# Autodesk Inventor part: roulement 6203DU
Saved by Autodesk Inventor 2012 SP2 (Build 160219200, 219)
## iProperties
Created: 2013-04
Part Number: roulement 6203DU
Material: Default
Document SubType Name: Modeling
Designer: papa
Density: 1 g/cm^3
Mass: 8.8924 g
Surface Area: 89.1385 cm^2
Volume: 8.8924 cm^3
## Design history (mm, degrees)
node "roulement 6203DU1"
node "roulement 6203DU"
node "roulement 6203DU_1"
node "roulement 6203DU_2"
node "roulement 6203DU_3"
node "roulement 6203DU_4"
node "roulement 6203DU_5"
node "roulement 6203DU_6"
node "roulement 6203DU_7"
node "roulement 6203DU_8"
node "roulement 6203DU_9"
node "roulement 6203DU_10"
node "roulement 6203DU_11"
node "roulement 6203DU_12"
node "roulement 6203DU_13"
node "Base1"
node "Base2"
node "Base3"
node "Base4"
node "Base5"
node "Base6"
node "Base7"
node "Base8"
node "Base9"
node "Base10"
node "Base11"
node "Base12"
node "Base13"
node "Base14"
